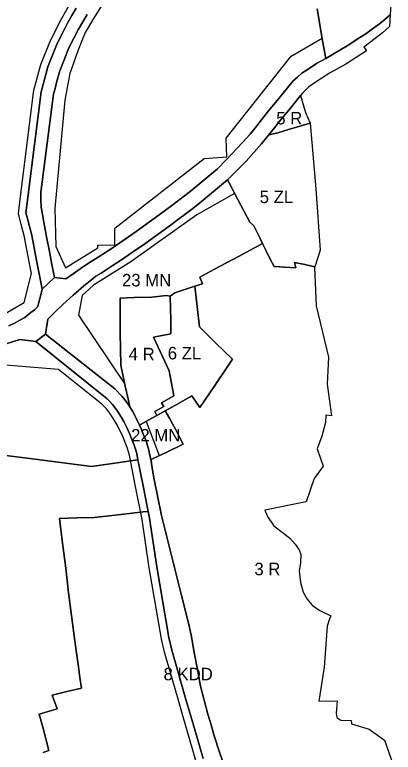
# Model space of a CAD drawing. Extents: x -294445 to -292055, y 21869 to 23693.
# Drawn here: x -292392 to -292089, y 22598 to 23188 of the extents above; entities that cross this region are included whole.
import ezdxf

# ---------------------------------------------------------------- set-up
doc = ezdxf.new("R2010")
doc.units = 0
for name, color, linetype in [('linie_rozgraniczajace', 7, 'Continuous'), ('linie_zabudowy_nieprzekraczalne', 7, 'Continuous'), ('oznaczenia_przeznaczen', 7, 'Continuous')]:
    doc.layers.add(name, color=color, linetype=linetype)

msp = doc.modelspace()

# ---------------------------------------------------------------- linework, layer by layer
at = {"layer": 'linie_rozgraniczajace'}
for points in [[(-292091.26, 23200.4), (-292091.981, 23188.232), (-292096.24, 23184.648), (-292100.5, 23181.063), (-292106.004, 23177.075), (-292111.508, 23173.086), (-292118.291, 23168.754), (-292125.074, 23164.422), (-292132.204, 23160.178), (-292139.335, 23155.935), (-292143.535, 23153.519), (-292144.476, 23158.938), (-292145.73, 23166.15), (-292147.925, 23178.781), (-292148.795, 23183.79), (-292150.443, 23193.27)], [(-292343.118, 23193.662), (-292346.59, 23187.721), (-292350.062, 23181.78), (-292354.227, 23173.627), (-292358.391, 23165.473), (-292362.091, 23156.072), (-292365.791, 23146.671), (-292368.506, 23136.74), (-292371.221, 23126.81), (-292376.566, 23084.496), (-292381.911, 23042.181), (-292383.4, 23029.81), (-292382.245, 23025.359), (-292381.089, 23020.909)], [(-292334.557, 23188.491), (-292337.921, 23182.735), (-292341.285, 23176.979), (-292345.275, 23169.169), (-292349.264, 23161.358), (-292352.776, 23152.435), (-292356.288, 23143.512), (-292358.838, 23134.184), (-292360.12, 23129.495), (-292361.388, 23124.856), (-292366.472, 23085.605), (-292371.555, 23046.355), (-292371.425, 23040.4), (-292371.294, 23034.446), (-292370.22, 23028.498), (-292369.146, 23022.55), (-292366.863, 23010.8), (-292364.58, 22999.05), (-292362.629, 22988.644), (-292360.679, 22978.238), (-292370.47, 22968.8), (-292372.591, 22979.657), (-292374.712, 22990.515), (-292376.894, 23001.834), (-292379.076, 23013.152), (-292380.083, 23017.031), (-292381.089, 23020.909), (-292382.245, 23025.359), (-292383.4, 23029.81), (-292381.911, 23042.181), (-292376.566, 23084.496), (-292371.221, 23126.81), (-292368.506, 23136.74), (-292365.791, 23146.671), (-292362.091, 23156.072), (-292358.391, 23165.473), (-292354.227, 23173.627), (-292350.062, 23181.78), (-292346.59, 23187.721), (-292343.118, 23193.662)], [(-292150.443, 23193.27), (-292148.795, 23183.79), (-292147.925, 23178.781), (-292145.73, 23166.15), (-292144.476, 23158.938), (-292143.535, 23153.519), (-292150.86, 23149.305), (-292156.725, 23145.464), (-292162.591, 23141.623), (-292166.024, 23138.578), (-292169.457, 23135.532), (-292172.928, 23131.302), (-292181.094, 23121.374), (-292189.26, 23111.445), (-292193.987, 23105.473), (-292198.713, 23099.5), (-292203.999, 23092.771), (-292209.985, 23086.155), (-292223.054, 23072.357), (-292230.137, 23065.177), (-292241.125, 23056.061), (-292252.114, 23046.946), (-292264.648, 23037.378), (-292273.991, 23030.365), (-292284.578, 23022.634), (-292295.166, 23014.904), (-292304.832, 23008.276), (-292314.499, 23001.648), (-292325.637, 22994.39), (-292329.938, 22991.715), (-292334.239, 22989.039), (-292339.997, 22985.055), (-292345.756, 22981.07), (-292351.594, 22977.102), (-292360.679, 22978.238), (-292362.629, 22988.644), (-292364.58, 22999.05), (-292366.863, 23010.8), (-292369.146, 23022.55), (-292370.22, 23028.498), (-292371.294, 23034.446), (-292371.425, 23040.4), (-292371.555, 23046.355), (-292366.472, 23085.605), (-292361.388, 23124.856), (-292360.12, 23129.495), (-292358.838, 23134.184), (-292356.288, 23143.512), (-292352.776, 23152.435), (-292349.264, 23161.358), (-292345.275, 23169.169), (-292341.285, 23176.979), (-292337.921, 23182.735), (-292334.557, 23188.491)], [(-292106.004, 23177.075), (-292100.5, 23181.063), (-292096.24, 23184.648), (-292091.981, 23188.232), (-292092.52, 23179.13), (-292098.04, 23174.07), (-292107.29, 23166.75), (-292112.89, 23162.44), (-292111.75, 23160.92), (-292110.76, 23159.61), (-292127.28, 23148.76), (-292140.61, 23141.66), (-292152.05, 23134.21), (-292156.97, 23130.87), (-292162.04, 23125.65), (-292163.66, 23123.68), (-292171.79, 23113.795), (-292179.92, 23103.91), (-292184.605, 23097.99), (-292189.29, 23092.07), (-292194.82, 23085.03), (-292201.034, 23078.163), (-292207.247, 23071.295), (-292214.631, 23063.809), (-292221.522, 23056.822), (-292222.092, 23056.259), (-292233.327, 23046.939), (-292244.64, 23037.554), (-292251.022, 23032.683), (-292257.405, 23027.811), (-292262.128, 23024.265), (-292266.85, 23020.72), (-292277.542, 23012.914), (-292288.233, 23005.108), (-292298.031, 22998.39), (-292307.829, 22991.672), (-292313.51, 22987.97), (-292319.191, 22984.268), (-292323.282, 22981.723), (-292327.374, 22979.178), (-292332.287, 22975.366), (-292337.2, 22971.555), (-292345.587, 22964.103), (-292353.975, 22956.652), (-292359.994, 22950.746), (-292366.013, 22944.84), (-292367.721, 22932.891), (-292375.64, 22926.87), (-292388.39, 22928.526), (-292398.467, 22925.492)], [(-292397.229, 22939.543), (-292391.99, 22941.853), (-292388.209, 22944.044), (-292384.367, 22946.27), (-292380.493, 22949.247), (-292376.619, 22952.225), (-292373.91, 22954.88), (-292373.551, 22956.254), (-292371.831, 22963.215), (-292370.47, 22968.8), (-292360.679, 22978.238), (-292351.594, 22977.102), (-292345.756, 22981.07), (-292339.997, 22985.055), (-292334.239, 22989.039), (-292329.938, 22991.715), (-292325.637, 22994.39), (-292314.499, 23001.648), (-292304.832, 23008.276), (-292295.166, 23014.904), (-292284.578, 23022.634), (-292273.991, 23030.365), (-292264.648, 23037.378), (-292252.114, 23046.946), (-292241.125, 23056.061), (-292230.137, 23065.177), (-292223.054, 23072.357), (-292209.985, 23086.155), (-292203.999, 23092.771), (-292198.713, 23099.5), (-292193.987, 23105.473), (-292189.26, 23111.445), (-292181.094, 23121.374), (-292172.928, 23131.302), (-292169.457, 23135.532), (-292166.024, 23138.578), (-292162.591, 23141.623), (-292156.725, 23145.464), (-292150.86, 23149.305), (-292143.535, 23153.519), (-292139.335, 23155.935), (-292132.204, 23160.178), (-292125.074, 23164.422), (-292118.291, 23168.754), (-292111.508, 23173.086), (-292106.004, 23177.075)], [(-292381.089, 23020.909), (-292380.083, 23017.031), (-292379.076, 23013.152), (-292376.894, 23001.834), (-292374.712, 22990.515), (-292372.591, 22979.657), (-292370.47, 22968.8), (-292371.831, 22963.215), (-292373.551, 22956.254), (-292373.91, 22954.88), (-292376.619, 22952.225), (-292380.493, 22949.247), (-292384.367, 22946.27), (-292388.209, 22944.044), (-292391.99, 22941.853), (-292397.229, 22939.543)], [(-292283.542, 22832.486), (-292282.542, 22832.914), (-292277.647, 22835.222), (-292270.045, 22838.806), (-292257.548, 22844.697), (-292260.704, 22850.823), (-292263.859, 22856.948), (-292266.077, 22861.001), (-292268.295, 22865.053), (-292271.963, 22871.54), (-292261.377, 22877.465), (-292250.79, 22883.39), (-292244.227, 22874.201), (-292232.752, 22891.067), (-292221.276, 22907.932), (-292218.187, 22912.849), (-292231.328, 22925.718), (-292244.469, 22938.586), (-292245.686, 22947.854), (-292246.999, 22959.532), (-292248.311, 22971.21), (-292242.18, 22973.22), (-292244.326, 22978.417), (-292232.474, 22984.754), (-292213.226, 22995.046), (-292193.978, 23005.337), (-292191.33, 23000), (-292188.105, 22993.495), (-292184.88, 22986.99), (-292176.21, 22986.42), (-292167.54, 22985.85), (-292168.369, 22990.301), (-292160.308, 22988.562), (-292152.246, 22986.822), (-292152.46, 22986.16), (-292151.04, 22955.47), (-292141.2, 22914.31), (-292142.22, 22892.95), (-292138.91, 22867.53), (-292143.35, 22868.11), (-292143.64, 22862.27), (-292146.51, 22851.11), (-292150.31, 22841), (-292145.56, 22827.11), (-292152.76, 22817.35), (-292159.06, 22798.64), (-292192.32, 22792.1), (-292190.1, 22786.89), (-292185.02, 22779.59), (-292177.42, 22773.73), (-292172.24, 22769.47), (-292167.95, 22764.74), (-292164.75, 22760.36), (-292163.55, 22756.55), (-292163.79, 22749.97), (-292164.89, 22743.07), (-292163.56, 22734), (-292161.66, 22726.31), (-292158.47, 22720.91), (-292154.33, 22715.86), (-292148.69, 22712.01), (-292139.53, 22707.52), (-292140.43, 22704.92), (-292142.3, 22699.15), (-292144.7, 22666.5), (-292149, 22639.3), (-292134.3, 22639.4), (-292135.1, 22629.2), (-292134.5, 22626), (-292131.4, 22624.1), (-292123.2, 22623.7), (-292122.9, 22621), (-292108.69, 22616.7), (-292096.57, 22608.04), (-292089.46, 22588.21)], [(-292375.64, 22926.87), (-292367.721, 22932.891), (-292340.027, 22910.968), (-292312.333, 22889.044), (-292306.692, 22883.264), (-292303.338, 22878.991), (-292300.33, 22874.61), (-292298.246, 22871.197), (-292296.161, 22867.785), (-292292.543, 22860.021), (-292291.21, 22857.16), (-292289.231, 22852.282), (-292287.251, 22847.403), (-292285.087, 22839.945), (-292284.209, 22835.705), (-292283.542, 22832.486), (-292283.265, 22831.111), (-292282.066, 22823.991), (-292280.801, 22816.518), (-292277.815, 22802.144), (-292274.829, 22787.769), (-292271.38, 22773.772), (-292265.581, 22750.341), (-292259.221, 22724.876), (-292252.86, 22699.41), (-292250.96, 22690.53), (-292248.67, 22678.236), (-292246.38, 22665.941), (-292245.005, 22658.556), (-292243.63, 22651.17), (-292237.83, 22628.82), (-292235.315, 22620.165), (-292232.8, 22611.51), (-292228.45, 22598.345), (-292224.1, 22585.18)], [(-292398.467, 22925.492), (-292388.39, 22928.526), (-292375.64, 22926.87), (-292347.09, 22904.037), (-292318.54, 22881.204), (-292316.382, 22878.935), (-292314.225, 22876.665), (-292311.401, 22873.068), (-292310.063, 22871.119), (-292308.725, 22869.17), (-292306.856, 22866.111), (-292304.988, 22863.052), (-292302.714, 22858.173), (-292300.441, 22853.294), (-292296.74, 22843.99), (-292295.762, 22840.691), (-292294.783, 22837.391), (-292293.779, 22832.289), (-292312.415, 22829.63), (-292331.05, 22826.97), (-292375.99, 22832.74), (-292420.93, 22838.51)], [(-292318.54, 22881.204), (-292347.09, 22904.037), (-292375.64, 22926.87)], [(-292241.69, 22593.21), (-292244.54, 22603.42), (-292248.045, 22615.325), (-292251.55, 22627.23), (-292255.88, 22642.41), (-292261.261, 22661.218), (-292266.642, 22680.026), (-292269.18, 22690.15), (-292273.975, 22718.435), (-292278.77, 22746.72), (-292281.676, 22766.138), (-292284.582, 22785.555), (-292285.651, 22790.986), (-292289.683, 22811.473), (-292293.779, 22832.289), (-292294.783, 22837.391), (-292295.762, 22840.691), (-292296.74, 22843.99), (-292300.441, 22853.294), (-292302.714, 22858.173), (-292304.988, 22863.052), (-292306.856, 22866.111), (-292308.725, 22869.17), (-292310.063, 22871.119), (-292311.401, 22873.068), (-292314.225, 22876.665), (-292316.382, 22878.935), (-292318.54, 22881.204)], [(-292420.93, 22838.51), (-292375.99, 22832.74), (-292331.05, 22826.97), (-292312.415, 22829.63), (-292293.779, 22832.289), (-292289.683, 22811.473), (-292285.651, 22790.986), (-292289.595, 22790.554), (-292307.256, 22788.618), (-292328.86, 22786.25), (-292342.695, 22785.795), (-292356.53, 22785.34), (-292354.06, 22765.48), (-292351.59, 22745.62), (-292350.44, 22735.75), (-292349.29, 22725.88), (-292346.875, 22707.595), (-292344.46, 22689.309), (-292342.895, 22677.925), (-292341.33, 22666.54), (-292340.171, 22658.111), (-292339.012, 22649.682), (-292350.766, 22646.806), (-292362.52, 22643.93), (-292358.54, 22633.1), (-292365.68, 22630.995), (-292372.82, 22628.89), (-292370.01, 22618.41), (-292367.6, 22609.095), (-292365.19, 22599.78), (-292369.55, 22598.15)], [(-292228.45, 22598.345), (-292232.8, 22611.51), (-292235.315, 22620.165), (-292237.83, 22628.82), (-292243.63, 22651.17), (-292245.005, 22658.556), (-292246.38, 22665.941), (-292248.67, 22678.236), (-292250.96, 22690.53), (-292252.86, 22699.41), (-292259.221, 22724.876), (-292265.581, 22750.341), (-292271.38, 22773.772), (-292274.829, 22787.769), (-292277.815, 22802.144), (-292280.801, 22816.518), (-292282.066, 22823.991), (-292283.265, 22831.111), (-292283.542, 22832.486)], [(-292369.55, 22598.15), (-292365.19, 22599.78), (-292367.6, 22609.095), (-292370.01, 22618.41), (-292372.82, 22628.89), (-292365.68, 22630.995), (-292358.54, 22633.1), (-292362.52, 22643.93), (-292350.766, 22646.806), (-292339.012, 22649.682), (-292340.171, 22658.111), (-292341.33, 22666.54), (-292342.895, 22677.925), (-292344.46, 22689.309), (-292346.875, 22707.595), (-292349.29, 22725.88), (-292350.44, 22735.75), (-292351.59, 22745.62), (-292354.06, 22765.48), (-292356.53, 22785.34), (-292342.695, 22785.795), (-292328.86, 22786.25), (-292307.256, 22788.618), (-292289.595, 22790.554), (-292285.651, 22790.986), (-292284.582, 22785.555), (-292281.676, 22766.138), (-292278.77, 22746.72), (-292273.975, 22718.435), (-292269.18, 22690.15), (-292266.642, 22680.026), (-292261.261, 22661.218), (-292255.88, 22642.41), (-292251.55, 22627.23), (-292248.045, 22615.325), (-292244.54, 22603.42), (-292241.69, 22593.21)], [(-292224.1, 22585.18), (-292228.45, 22598.345)]]:
    msp.add_lwpolyline(points, dxfattribs=at)
for points in [[(-292189.29, 23092.07), (-292184.605, 23097.99), (-292179.92, 23103.91), (-292171.79, 23113.795), (-292163.66, 23123.68), (-292159.7, 23110.24), (-292155.96, 23101.79), (-292173.22, 23096.72), (-292181.83, 23094.03), (-292185.56, 23093.05)], [(-292222.092, 23056.259), (-292221.522, 23056.822), (-292214.631, 23063.809), (-292207.247, 23071.295), (-292201.034, 23078.163), (-292194.82, 23085.03), (-292189.29, 23092.07), (-292185.56, 23093.05), (-292181.83, 23094.03), (-292173.22, 23096.72), (-292155.96, 23101.79), (-292151.47, 23049.08), (-292147.98, 23000), (-292152.246, 22986.822), (-292160.308, 22988.562), (-292168.369, 22990.301), (-292167.54, 22985.85), (-292176.21, 22986.42), (-292184.88, 22986.99), (-292188.105, 22993.495), (-292191.33, 23000), (-292193.978, 23005.337), (-292196.19, 23009.795), (-292201.05, 23019.59), (-292204.35, 23022.34), (-292206.46, 23026.35), (-292213.68, 23040.165), (-292220.9, 23053.98)], [(-292367.721, 22932.891), (-292366.013, 22944.84), (-292359.994, 22950.746), (-292353.975, 22956.652), (-292345.587, 22964.103), (-292337.2, 22971.555), (-292332.287, 22975.366), (-292327.374, 22979.178), (-292323.282, 22981.723), (-292319.191, 22984.268), (-292313.51, 22987.97), (-292307.829, 22991.672), (-292298.031, 22998.39), (-292288.233, 23005.108), (-292277.542, 23012.914), (-292266.85, 23020.72), (-292262.128, 23024.265), (-292257.405, 23027.811), (-292251.022, 23032.683), (-292244.64, 23037.554), (-292233.327, 23046.939), (-292222.092, 23056.259), (-292220.9, 23053.98), (-292213.68, 23040.165), (-292206.46, 23026.35), (-292204.35, 23022.34), (-292201.05, 23019.59), (-292196.19, 23009.795), (-292193.978, 23005.337), (-292213.226, 22995.046), (-292232.474, 22984.754), (-292244.326, 22978.417), (-292242.18, 22973.22), (-292248.311, 22971.21), (-292264.208, 22965.997), (-292267.99, 22963.15), (-292270.97, 22963.78), (-292282.78, 22962.39), (-292296.684, 22962.046), (-292307.91, 22961.77), (-292308.06, 22944.47), (-292307.89, 22934.23), (-292307.675, 22921.12), (-292307.46, 22908.01), (-292303.895, 22891.31), (-292301.686, 22880.96), (-292300.33, 22874.61), (-292303.338, 22878.991), (-292306.692, 22883.264), (-292312.333, 22889.044), (-292340.027, 22910.968)], [(-292281.322, 22930.385), (-292267.349, 22933.112), (-292267.461, 22940.979), (-292267.526, 22944.478), (-292267.737, 22952.976), (-292267.99, 22963.15), (-292264.208, 22965.997), (-292248.311, 22971.21), (-292246.999, 22959.532), (-292245.686, 22947.854), (-292244.469, 22938.586), (-292231.328, 22925.718), (-292218.187, 22912.849), (-292221.276, 22907.932), (-292232.752, 22891.067), (-292244.227, 22874.201), (-292250.79, 22883.39), (-292261.377, 22877.465), (-292271.963, 22871.54), (-292278.715, 22867.761), (-292280.209, 22870.928), (-292276.69, 22872.899), (-292273.17, 22874.87), (-292274.88, 22877.92), (-292265.099, 22883.396), (-292268.74, 22903.57)], [(-292308.06, 22944.47), (-292307.91, 22961.77), (-292296.684, 22962.046), (-292282.78, 22962.39), (-292270.97, 22963.78), (-292267.99, 22963.15), (-292267.737, 22952.976), (-292267.526, 22944.478), (-292267.461, 22940.979), (-292267.349, 22933.112), (-292281.322, 22930.385), (-292268.74, 22903.57), (-292265.099, 22883.396), (-292274.88, 22877.92), (-292273.17, 22874.87), (-292276.69, 22872.899), (-292280.209, 22870.928), (-292278.715, 22867.761), (-292285.629, 22863.891), (-292292.543, 22860.021), (-292296.161, 22867.785), (-292298.246, 22871.197), (-292300.33, 22874.61), (-292301.686, 22880.96), (-292303.895, 22891.31), (-292307.46, 22908.01), (-292307.675, 22921.12), (-292307.89, 22934.23)], [(-292292.543, 22860.021), (-292285.629, 22863.891), (-292278.715, 22867.761), (-292271.963, 22871.54), (-292268.295, 22865.053), (-292266.077, 22861.001), (-292263.859, 22856.948), (-292260.704, 22850.823), (-292257.548, 22844.697), (-292270.045, 22838.806), (-292277.647, 22835.222), (-292282.542, 22832.914), (-292283.542, 22832.486), (-292284.209, 22835.705), (-292285.087, 22839.945), (-292287.251, 22847.403), (-292289.231, 22852.282), (-292291.21, 22857.16)]]:
    msp.add_lwpolyline(points, close=True, dxfattribs=at)
at = {"layer": 'linie_zabudowy_nieprzekraczalne'}
for points in [[(-292290.967, 23247.022), (-292329.421, 23185.389), (-292336.019, 23174.099), (-292341.972, 23159.567), (-292348.191, 23141.389), (-292352.433, 23120.199), (-292360.352, 23033.387), (-292359.504, 23003.058), (-292359.504, 23003.058), (-292359.504, 23003.058), (-292351.809, 22985.894), (-292325.963, 23001.873), (-292325.963, 23004.136), (-292312.372, 23004.388), (-292312.372, 23017.715), (-292240.895, 23073.286), (-292222.774, 23074.794), (-292223.134, 23089.544), (-292171.132, 23155.195), (-292146.341, 23169.667)], [(-292408.656, 22944.635), (-292384.858, 22958.166), (-292378.974, 22981.491), (-292380.602, 22989.372), (-292384.931, 23011.829), (-292386.897, 23019.401), (-292389.493, 23029.4), (-292387.866, 23042.916), (-292377.12, 23127.983), (-292371.493, 23148.566), (-292363.867, 23167.942), (-292355.328, 23184.661), (-292348.254, 23196.765)], [(-292216.48, 23045.523), (-292246.644, 23028.406), (-292299.492, 22990.671), (-292329.391, 22971.968), (-292338.386, 22963.904), (-292341.413, 22948.129), (-292304.196, 22892.72)], [(-292295.967, 22812.331), (-292300.616, 22835.956), (-292302.415, 22842.024), (-292305.952, 22850.916), (-292310.284, 22860.212), (-292313.762, 22865.906), (-292316.239, 22869.514), (-292318.769, 22872.737), (-292322.606, 22876.773), (-292357.393, 22904.594), (-292429.359, 22910.43)], [(-292287.107, 22863.064), (-292276.737, 22835.651)], [(-292478.651, 22448.833), (-292408.647, 22453.378), (-292399.773, 22454.1), (-292245.491, 22468.964), (-292244.6, 22466.296), (-292244.6, 22466.296), (-292208.258, 22478.276), (-292219.557, 22503.736), (-292225.508, 22516.339), (-292230.157, 22528.975), (-292237.814, 22556.744), (-292244.621, 22581.395), (-292250.308, 22601.766), (-292257.313, 22625.56), (-292261.649, 22640.762), (-292272.438, 22678.471), (-292275.057, 22688.917), (-292284.695, 22745.774), (-292290.496, 22784.531), (-292295.967, 22812.331)]]:
    msp.add_lwpolyline(points, dxfattribs=at)

# ---------------------------------------------------------------- texts
at = {"layer": 'oznaczenia_przeznaczen'}
for s, p in [('5 R', (-292183.078, 23100.666)), ('5 ZL', (-292196.314, 23037.694)), ('23 MN', (-292306.545, 22971.054)), ('4 R', (-292301.2, 22911.91)), ('6 ZL', (-292269.926, 22912.649)), ('22 MN', (-292299.27, 22846.959)), ('3 R', (-292200.587, 22739.918)), ('8 KDD', (-292273.268, 22655.887))]:
    msp.add_text(s, height=10, dxfattribs=at).set_placement(p)

doc.saveas('drawing.dxf')
